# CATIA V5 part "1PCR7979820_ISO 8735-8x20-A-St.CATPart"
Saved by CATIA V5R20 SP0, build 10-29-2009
Part number: 1PCR7979820_ISO 8735-8x20-A-St
Revision: ANY
Definition: UNKNOWN
Nomenclature: 1PCR7979820_ISO 8735-8x20-A-St
Source: Unknown
Bounding box of the stored display mesh (mm): x 0 to 20, y -3.804 to 3.804, z -4 to 4
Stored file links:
  C:\Users\Utente\Desktop\IO LAVORO\3D X SITO CF\CUMSA\3D files RC\RC 164008\1PCR7979820_ISO 8735-8x20-A-St.CATPart
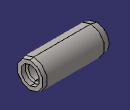
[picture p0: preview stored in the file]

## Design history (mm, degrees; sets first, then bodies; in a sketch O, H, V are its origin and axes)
Body1 "TypeA" (main body)
  Solid1: solid without history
